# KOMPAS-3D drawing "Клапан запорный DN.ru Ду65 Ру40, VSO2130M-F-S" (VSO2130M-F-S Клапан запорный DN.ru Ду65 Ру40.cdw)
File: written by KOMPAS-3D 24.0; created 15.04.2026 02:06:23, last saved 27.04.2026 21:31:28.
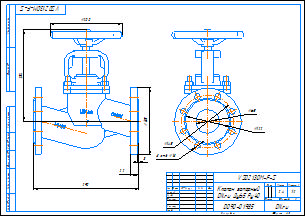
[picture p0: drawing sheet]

Document properties: Автор: DN.ru; Форматы листов документа: A3; Полное имя файла: VSO2130M-F-S Клапан запорный DN.ru Ду65 Ру40.m3d; Масса: 24; Наименование: Клапан запорный DN.ru Ду65 Ру40; Количество листов документа: 1; Примечание: D090-01985

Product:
- Part/product: Клапан запорный DN.ru Ду65 Ру40  | designation VSO2130M-F-S
    Масса: 24
    Раздел спецификации: Прочие изделия
    Примечание: D090-01985

Views: Вид 1, Вид:1, Проекционный вид 2
Referenced files in C:\Работа\VSO2130M-F-S Клапан запорный DN.ru\DN15\: VSO2130M-F-S DN15 PN40  Клапан запорный сильфонный DN.ru.m3d
Referenced files in C:\Работа\VSO2130M-F-S Клапан запорный DN.ru Ду-x Ру40\DN65\: VSO2130M-F-S Клапан запорный DN.ru Ду65 Ру40.m3d
Referenced files in C:\Program Files\ASCON\KOMPAS-3D v24\Templates\: Чертеж_DN.ru.cdt
Referenced files in C:\Работа\ГОТОВЫЕ ИСХОДНИКИ\VSO2130M-F-S Клапан запорный сальниковый DN.ru Ду15-100 Ру40\DN65\: VSO2130M-F-S Клапан запорный DN.ru Ду65 Ру40.m3d
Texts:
  VSO2130M-F-S
  Чертеж_DN.ru.cdt
  Клапан запорный
  DN.ru Ду65 Ру40
  Клапан запорный DN.ru Ду65 Ру40
  VSO2130M-F-S Клапан запорный DN.ru Ду65 Ру40
Dimensions and other numbers on the sheet: 0; 3; 2; 4; 185; 22; 254; 200; 290; 5; 65; 122; 145; 8 отв.; 18; 1:2; 1; 24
